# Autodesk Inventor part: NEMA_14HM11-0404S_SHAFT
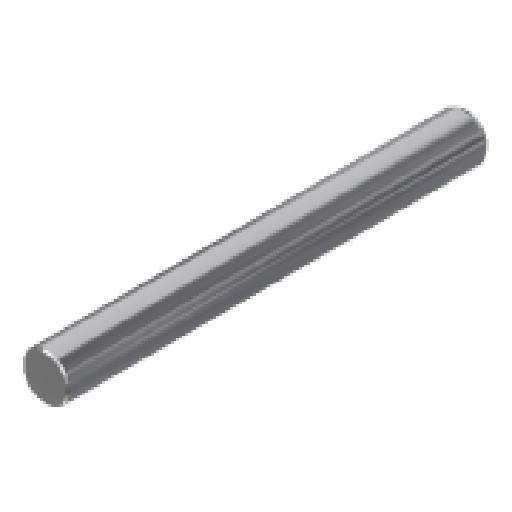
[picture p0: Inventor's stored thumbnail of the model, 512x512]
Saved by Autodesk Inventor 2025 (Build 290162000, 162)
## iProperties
Created: 2019-11
Part Number: NEMA_14HM11-0404S_SHAFT
Material: Générique
Document SubType Name: Modeling
Designer: thoma
Density: 1 g/cm^3
Appearance: Aluminium - Plat
Author: thoma
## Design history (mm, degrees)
sketch "Esquisse1"
  geometry: C1 r 2.5 at (0, 0); 1 further point
  constraints: 1 centre point, 1 coincident
  dimensions: "d0" = 5 diameter of C1
extrude "Extrusion1" new body sketch "Esquisse1" distance "d1" = 45; taper "d2" = 0 deg
chamfer "Chanfrein1" distance "d3" = 0.2; stored, may be unused: second distance "d4" = 2, angle "d5" = 45 deg
chamfer "Chanfrein2" distance "d6" = 0.3; stored, may be unused: second distance "d7" = 2, angle "d8" = 60 deg
sketch "Esquisse2"
  geometry: L1 (-2.5, 0)-(2, 0); L2 (2, 0)-(2, 1.5); L3 (2, 0)-(2, -1.5); A1 r 2.5 centre (0, 0) between (2, -1.5) and (2, 1.5); 2 further points
  constraints: 6 end point, 2 point on circle, 1 centre point, 1 coincident, 1 horizontal, 1 horizontal alignment, 1 point on line, 1 vertical, 1 other
  dimensions: "d9" = 4.5 distance of L1.start L1.end
extrude "Extrusion2" cut sketch "Esquisse2" distance "d10" = 15; taper "d11" = 0 deg
fillet "Congé1" dims "d12" = 0.1
node "Solide1"
